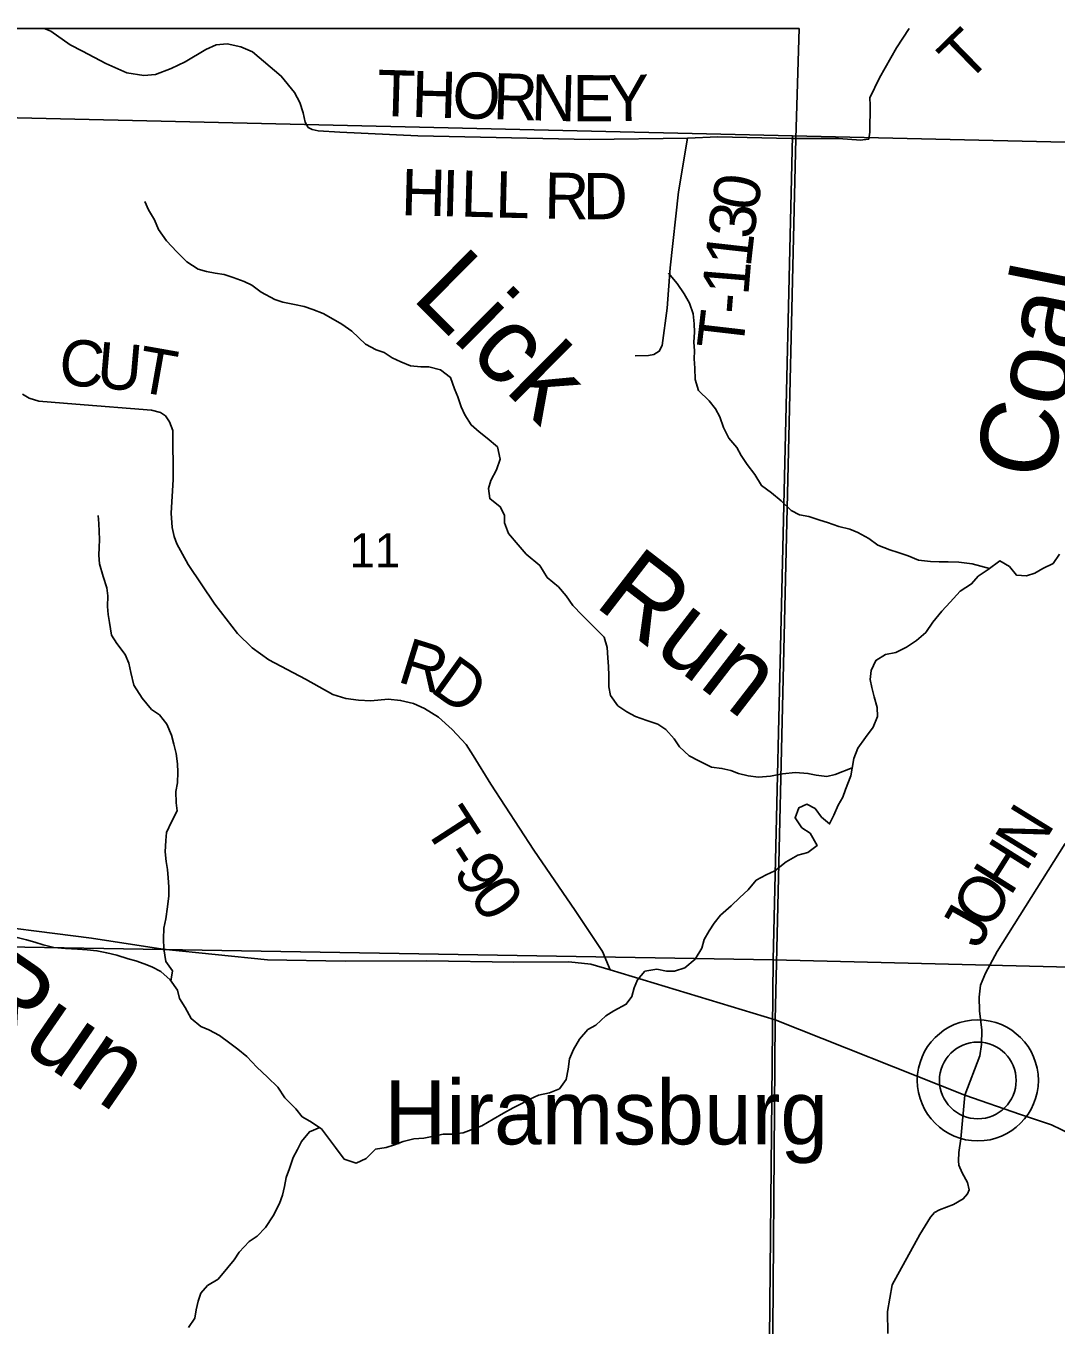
# Model space of a CAD drawing. Extents: x -452339 to 6403467, y -1 to 1814750.
# Drawn here: x -70035 to -63350, y 1554727 to 1563158 of the extents above; entities that cross this region are included whole.
import ezdxf

# ---------------------------------------------------------------- set-up
doc = ezdxf.new("R2010")
doc.units = 0
for name, color, linetype in [('GM_X_Adjacent_County_Text', 7, 'Continuous'), ('GM_X_Corporation', 7, 'Continuous'), ('GM_X_County_Road', 7, 'Continuous'), ('GM_X_County_Road_Text', 7, 'Continuous'), ('GM_X_County_ROW', 7, 'Continuous'), ('GM_X_Major_Lake', 7, 'Continuous'), ('GM_X_Major_Lake_Text', 7, 'Continuous'), ('GM_X_Section', 7, 'Continuous'), ('GM_X_Section_Text', 7, 'Continuous'), ('GM_X_Township_Road_Text', 7, 'Continuous'), ('GM_X_Unincorporated_Location', 7, 'Continuous')]:
    doc.layers.add(name, color=color, linetype=linetype)

msp = doc.modelspace()

# ---------------------------------------------------------------- linework, layer by layer
at = {"layer": 'GM_X_County_Road'}
msp.add_lwpolyline([(-63191, 1555935.7), (-63379.6, 1556027.1), (-63580.2, 1556094.3), (-63942.9, 1556218.4), (-65173, 1556706.7), (-66244.5, 1557031.8), (-66368.8, 1557069.7), (-66513.1, 1557085.1), (-66869.7, 1557081.3), (-67432.7, 1557090.6), (-67963.6, 1557088.1), (-68468.5, 1557097.7), (-69147.9, 1557166.6), (-69611, 1557238.6), (-70462.9, 1557344.8)], dxfattribs=at)
at = {"layer": 'GM_X_County_Road_Text'}
for radius in [392.8, 249]:
    msp.add_circle((-63857.5, 1556314.4), radius, dxfattribs=at)
at = {"layer": 'GM_X_County_ROW'}
for points in [[(-65068.9, 1562427.7), (-65544.7, 1562437.4), (-65741.6, 1562428.6), (-66376.5, 1562420.9), (-67492.1, 1562444.3), (-67998.1, 1562468.4), (-68138.1, 1562477.3), (-68178.1, 1562485), (-68204.2, 1562498.9), (-68222.5, 1562532.8), (-68236.9, 1562594.8), (-68257.3, 1562660.7), (-68291.8, 1562726.6), (-68378.5, 1562832), (-68565.5, 1562988.8), (-68641.7, 1563022.3), (-68729.8, 1563041.6), (-68801.7, 1563035.1), (-68867.5, 1563004.5), (-69002.9, 1562925.3), (-69092.5, 1562882.6), (-69194.2, 1562843.7), (-69270.1, 1562837.1), (-69380.2, 1562854.3), (-69516.6, 1562913.3), (-69669.1, 1562994.3), (-69749.3, 1563035.7), (-69873.9, 1563124.9), (-69916.9, 1563140.5)], [(-64303.6, 1563140.5), (-64385.6, 1563015.4), (-64496.1, 1562820.2), (-64558.9, 1562692.2), (-64557.1, 1562643), (-64558.9, 1562469), (-64565.9, 1562423.4), (-64603.6, 1562418.2)], [(-66080.9, 1561017.1), (-65994.9, 1561019.8), (-65960.9, 1561026.1), (-65925.1, 1561046.4), (-65905.3, 1561084.6), (-65873.1, 1561325.3), (-65855.1, 1561587.9), (-65800.7, 1562081.2), (-65741.6, 1562428.6)], [(-64603.6, 1562418.2), (-64616.9, 1562416.3), (-64762.7, 1562426.9), (-65038.6, 1562427.1), (-65068.9, 1562427.7)], [(-66244.5, 1557031.8), (-66293, 1557151.8), (-66470.8, 1557416.9), (-66739.5, 1557809.6), (-67018.4, 1558236.3), (-67133.7, 1558423.7), (-67178.2, 1558493.5), (-67268.9, 1558593), (-67357.4, 1558672.5), (-67449.7, 1558727.9), (-67520, 1558761.4), (-67604.1, 1558780.8), (-67684.1, 1558788.2), (-67797.9, 1558777.3), (-67877.9, 1558782.7), (-67960, 1558794), (-68044.1, 1558819.4), (-68220.8, 1558918.3), (-68459.6, 1559044.6), (-68568.1, 1559121.9), (-68662.7, 1559215.4), (-68810, 1559404.6), (-68981.7, 1559661.8), (-69056.7, 1559797.5), (-69073, 1559845.4), (-69087.4, 1559903.4), (-69092.1, 1559995.6), (-69079.6, 1560214.1), (-69081.9, 1560532.6), (-69104.3, 1560588.6), (-69130.5, 1560628.4), (-69162.7, 1560648.2), (-69220.7, 1560663.8), (-69712.8, 1560704), (-69952.8, 1560722.2), (-70015, 1560741.7), (-70057.1, 1560767.5)], [(-63942.9, 1556218.4), (-63845.2, 1556474.6), (-63834.4, 1556546.9), (-63832.1, 1556641.1), (-63846.2, 1556765.2), (-63847.8, 1556855.3), (-63839.1, 1556931.6), (-63808.5, 1557010.3), (-63733, 1557152), (-63291.2, 1557851.4)]]:
    msp.add_lwpolyline(points, dxfattribs=at)
at = {"layer": 'GM_X_Section'}
msp.add_lwpolyline([(-63942.9, 1556218.4), (-63968.8, 1555936), (-63980.8, 1555845.8), (-63982.7, 1555793.7), (-63980.7, 1555763.7), (-63958.6, 1555715.6), (-63924.6, 1555651.6), (-63914.6, 1555605.5), (-63924.5, 1555577.4), (-63952.5, 1555545.3), (-64016.4, 1555509.2), (-64106.4, 1555475), (-64138.4, 1555456.9), (-64164.3, 1555426.8), (-64234.2, 1555314.5), (-64413.9, 1554988.8), (-64443.7, 1554815.5), (-64441.5, 1554672.4)], dxfattribs=at)
at = {"layer": 'GM_X_Section_Text'}
msp.add_lwpolyline([(-65016.9, 1563140.5), (-75200.9, 1563140.5), (-75200.9, 1547985.7), (-65249.9, 1547985.7), (-65216.2, 1549772.3), (-65189.8, 1554406.9), (-65173, 1556706.7), (-65038.6, 1562427.1)], close=True, dxfattribs=at)
at = {"layer": 'GM_X_Township_Road_Text'}
for points in [[(-64672.2, 1558343.1), (-64782.4, 1558300), (-64838.3, 1558287.8), (-64906.3, 1558295.5), (-64960.3, 1558307.4), (-65040.3, 1558313.1), (-65124.3, 1558304.8), (-65204.2, 1558288.5), (-65280.1, 1558282.2), (-65348.1, 1558292), (-65410.2, 1558305.8), (-65460.2, 1558325.7), (-65518.2, 1558339.5), (-65586.2, 1558347.3), (-65668.3, 1558389.1), (-65730.4, 1558420.9), (-65794.5, 1558478.8), (-65828.7, 1558530.7), (-65882.9, 1558592.6), (-65934.9, 1558626.5), (-66005, 1558650.3), (-66079, 1558676.1), (-66135.1, 1558705.9), (-66193.2, 1558745.8), (-66241.4, 1558811.7), (-66251.5, 1558869.7), (-66251.8, 1558941.9), (-66254, 1558999.9), (-66258.1, 1559056), (-66262.3, 1559124.1), (-66282.5, 1559192.1), (-66352.7, 1559260), (-66424.9, 1559333.8), (-66487.1, 1559397.7), (-66529.3, 1559459.6), (-66579.4, 1559517.5), (-66651.6, 1559579.4), (-66699.8, 1559655.3), (-66788, 1559729.1), (-66840.1, 1559791), (-66904.3, 1559864.9), (-66930.5, 1559932.9), (-66928.7, 1559983), (-66956.8, 1560037), (-67025, 1560090.8), (-67033.2, 1560154.9), (-67017.3, 1560207), (-66981.6, 1560277.2), (-66957.8, 1560345.4), (-66974, 1560425.4), (-67042.2, 1560483.3), (-67094.3, 1560523.2), (-67146.4, 1560569), (-67186.6, 1560633), (-67210.7, 1560687), (-67232.9, 1560751), (-67253.1, 1560803), (-67279.3, 1560877), (-67345.4, 1560926.8), (-67421.4, 1560946.6), (-67473.4, 1560946.4), (-67539.4, 1560952.2), (-67601.5, 1560978), (-67659.5, 1561003.8), (-67711.6, 1561037.7), (-67763.6, 1561055.6), (-67831.7, 1561093.4), (-67919.9, 1561177.2), (-67986, 1561223), (-68056.1, 1561262.8), (-68106.2, 1561290.7), (-68174.3, 1561318.5), (-68230.3, 1561336.3), (-68292.3, 1561350.1), (-68368.3, 1561365.9), (-68420.4, 1561381.7), (-68508.5, 1561429.5), (-68568.6, 1561475.3), (-68618.6, 1561499.2), (-68690.7, 1561525), (-68748.7, 1561544.8), (-68806.7, 1561552.6), (-68864.7, 1561564.4), (-68916.8, 1561580.3), (-68990.9, 1561626.1), (-69057, 1561691.9), (-69123.2, 1561763.8), (-69175.4, 1561837.7), (-69201.6, 1561899.7), (-69239.8, 1561963.6), (-69263.9, 1562017.6)], [(-63782.6, 1559637.1), (-63894.9, 1559666.9), (-63980.9, 1559678.6), (-64050.9, 1559680.4), (-64108.9, 1559680.2), (-64164.9, 1559682), (-64242.9, 1559691.7), (-64308.9, 1559719.6), (-64375, 1559741.4), (-64429, 1559757.2), (-64507.1, 1559789), (-64565.2, 1559830.8), (-64637.3, 1559870.6), (-64689.3, 1559892.5), (-64759.3, 1559910.3), (-64833.4, 1559936.1), (-64883.4, 1559949.9), (-64953.5, 1559973.7), (-65015.5, 1559985.5), (-65069.5, 1560013.4), (-65133.7, 1560075.2), (-65195.8, 1560127.1), (-65262, 1560174.9), (-65304.2, 1560246.9), (-65354.3, 1560312.8), (-65392.5, 1560370.7), (-65420.6, 1560422.7), (-65472.8, 1560482.6), (-65509, 1560552.6), (-65531.2, 1560620.6), (-65559.4, 1560672.6), (-65601.5, 1560724.5), (-65669.7, 1560792.3), (-65691.9, 1560864.4), (-65694.1, 1560936.4), (-65698.3, 1560998.5), (-65696.4, 1561048.6), (-65700.6, 1561104.6), (-65696.8, 1561170.7), (-65699, 1561224.8), (-65705.2, 1561288.8), (-65729.4, 1561358.8), (-65763.5, 1561418.8), (-65809.7, 1561486.7), (-65865.9, 1561552.6)], [(-69094.7, 1556959), (-69084.7, 1557025.3), (-69126.9, 1557085.2), (-69141.1, 1557169.3), (-69143.3, 1557233.4), (-69141.6, 1557303.5), (-69127.7, 1557363.7), (-69116, 1557441.8), (-69108.2, 1557512), (-69108.4, 1557570), (-69112.6, 1557630.1), (-69116.7, 1557684.2), (-69124.9, 1557734.2), (-69131.1, 1557798.3), (-69127.3, 1557872.4), (-69123.5, 1557924.5), (-69091.7, 1557992.7), (-69053.9, 1558065), (-69060.1, 1558115), (-69062.3, 1558189.1), (-69052.5, 1558245.2), (-69050.7, 1558315.4), (-69050.9, 1558369.4), (-69061.1, 1558435.5), (-69075.3, 1558497.5), (-69091.4, 1558555.6), (-69121.6, 1558625.6), (-69169.8, 1558687.5), (-69219.9, 1558721.4), (-69282.1, 1558795.3), (-69334.3, 1558879.2), (-69354.6, 1558961.3), (-69366.8, 1559023.3), (-69390.9, 1559079.3), (-69445.1, 1559149.2), (-69479.3, 1559203.2), (-69493.5, 1559285.3), (-69501.7, 1559337.3), (-69505.8, 1559389.4), (-69504.1, 1559459.5), (-69510.2, 1559511.5), (-69534.4, 1559585.6), (-69558.7, 1559667.6), (-69562.8, 1559723.7), (-69561, 1559773.7), (-69557.2, 1559825.8), (-69561.5, 1559929.9), (-69567.6, 1559980)], [(-63327.4, 1559728.9), (-63369.2, 1559668.7), (-63435, 1559636.4), (-63486.9, 1559606.2), (-63540.9, 1559590), (-63606.8, 1559593.8), (-63653, 1559649.7), (-63715.1, 1559685.5), (-63790.9, 1559631.2), (-63854.7, 1559586.9), (-63898.5, 1559536.7), (-63972.4, 1559490.4), (-64036.1, 1559418.1), (-64091.9, 1559359.8), (-64149.7, 1559287.5), (-64195.5, 1559221.3), (-64255.3, 1559169), (-64321.1, 1559126.7), (-64389, 1559092.4), (-64456.9, 1559078.2), (-64518.8, 1559039.9), (-64550.6, 1558975.7), (-64556.4, 1558915.6), (-64546.2, 1558863.6), (-64530, 1558803.5), (-64511.8, 1558735.5), (-64507.7, 1558675.4), (-64537.4, 1558607.2), (-64587.2, 1558541), (-64637, 1558470.7), (-64662.8, 1558404.5), (-64672.6, 1558340.4), (-64682.4, 1558290.3), (-64716.1, 1558202.1), (-64734, 1558151.9), (-64763.8, 1558101.8), (-64791.6, 1558035.6), (-64819.4, 1557979.4), (-64871.5, 1558023.3), (-64913.7, 1558079.2), (-64967.7, 1558107.1), (-65019.6, 1558082.8), (-65043.4, 1558018.7), (-64999.2, 1557954.7), (-64945.2, 1557918.9), (-64900.9, 1557838.9), (-64960.8, 1557792.6), (-65024.7, 1557776.4), (-65100.5, 1557732.1), (-65174.3, 1557675.7), (-65230.2, 1557649.5), (-65296.1, 1557613.2), (-65347.9, 1557551), (-65401.7, 1557502.7), (-65457.5, 1557448.4), (-65527.3, 1557386.1), (-65569.1, 1557335.9), (-65600.9, 1557285.7), (-65634.7, 1557229.5), (-65648.6, 1557173.4), (-65692.3, 1557101.1), (-65758.1, 1557044.8), (-65826, 1557022.5), (-65878, 1557024.4), (-65940, 1557036.2), (-66018, 1557023.9), (-66065.8, 1556967.6), (-66087.6, 1556915.5), (-66103.4, 1556859.3), (-66139.3, 1556809.1), (-66219.1, 1556766.8), (-66271, 1556732.6), (-66336.8, 1556672.3), (-66388.7, 1556646), (-66442.4, 1556581.8), (-66482.2, 1556515.5), (-66508, 1556455.4), (-66515.8, 1556387.2), (-66529.6, 1556321.1), (-66573.4, 1556260.9), (-66637.3, 1556234.6), (-66709.2, 1556218.3), (-66765.1, 1556192.1), (-66817, 1556163.9), (-66872.9, 1556137.6), (-66936.8, 1556101.4), (-67002.6, 1556063.1), (-67076.4, 1556020.8), (-67146.3, 1555994.5), (-67198.3, 1555974.3), (-67272.2, 1555966), (-67328.2, 1555965.8)], [(-67328.2, 1555965.8), (-67400.1, 1555951.6), (-67454, 1555939.4), (-67518, 1555935.1), (-67587.9, 1555918.9), (-67643.8, 1555896.6), (-67697.8, 1555878.4), (-67767.7, 1555868.2), (-67827.5, 1555807.9), (-67891.4, 1555777.6), (-67969.4, 1555803.4), (-68025.6, 1555879.3), (-68077.8, 1555949.2), (-68118, 1556001.2), (-68192.1, 1556051), (-68242.1, 1556078.8), (-68284.3, 1556130.8), (-68354.5, 1556200.6), (-68400.7, 1556270.6), (-68468.8, 1556336.4), (-68537, 1556400.3), (-68601.2, 1556470.2), (-68659.3, 1556518), (-68711.4, 1556555.9), (-68779.6, 1556605.7), (-68847.6, 1556643.6), (-68899.7, 1556663.4), (-68963.8, 1556715.3), (-69002, 1556787.2), (-69038.2, 1556845.2), (-69052.3, 1556899.2), (-69100.5, 1556967.2), (-69160.7, 1557021), (-69218.8, 1557050.9), (-69268.8, 1557070.7), (-69322.8, 1557090.6), (-69372.9, 1557104.4), (-69444.9, 1557128.2), (-69510.9, 1557142), (-69574.9, 1557155.8), (-69638.9, 1557161.6), (-69700.9, 1557165.4), (-69778.9, 1557171.1), (-69854.9, 1557176.9), (-69922.9, 1557194.7), (-69978.9, 1557212.5), (-70033, 1557226.4), (-70101, 1557244.1)], [(-68128, 1556007.9), (-68195.9, 1555980.9), (-68247.6, 1555918.6), (-68273.5, 1555866.4), (-68301.3, 1555814.3), (-68325.1, 1555742.1), (-68346.9, 1555683.9), (-68356.7, 1555625.8), (-68370.5, 1555569.7), (-68390.4, 1555515.5), (-68430.1, 1555435.3), (-68479.8, 1555359), (-68535.6, 1555304.7), (-68587.5, 1555268.5), (-68651.3, 1555200.2), (-68683.1, 1555150), (-68724.9, 1555099.8), (-68788.7, 1555025.5), (-68856.5, 1554983.2), (-68900.4, 1554933), (-68918.2, 1554880.9), (-68930, 1554824.7), (-68939.9, 1554772.6), (-68979.6, 1554710.4)]]:
    msp.add_lwpolyline(points, dxfattribs=at)
at = {"layer": 'GM_X_Unincorporated_Location'}
for points in [[(-65059.8, 1562444.8), (-65186.4, 1557097.3), (-70427.3, 1557184.9), (-70371.2, 1562567.6)], [(-59752.5, 1562321.9), (-59755.1, 1561995.7), (-59844.9, 1556964.8), (-65186.4, 1557097.3), (-65059.8, 1562444.8)], [(-70427.3, 1557184.9), (-65186.4, 1557097.3), (-65238.6, 1551724.6), (-70513.9, 1551851.8)], [(-65186.4, 1557097.3), (-59844.9, 1556964.8), (-59852, 1556682.6), (-59917, 1551575.9), (-65238.6, 1551724.6)]]:
    msp.add_lwpolyline(points, close=True, dxfattribs=at)

# ---------------------------------------------------------------- texts
at = {"layer": 'GM_X_Adjacent_County_Text'}
msp.add_text('Hiramsburg', height=416.67, rotation=0.00001, dxfattribs=at).set_placement((-67709.1, 1555899.4))
at = {"layer": 'GM_X_Corporation'}
for s, height, rotation, p in [('Lick', 500.1, 315.21429, (-67539.8, 1561391.2)), ('Coal', 500.16, 78.77792, (-63391.1, 1560194.8)), ('Run', 500.11, 322.31583, (-66355.9, 1559400.6)), ('Run', 500.11, 325.43818, (-70472.2, 1556798))]:
    msp.add_text(s, height=height, rotation=rotation, dxfattribs=at).set_placement(p)
at = {"layer": 'GM_X_Major_Lake'}
msp.add_text('11', height=220.83, rotation=0.00001, dxfattribs=at).set_placement((-67935.7, 1559644.3))
at = {"layer": 'GM_X_Major_Lake_Text'}
for s, rotation, p in [('T', 44.32418, (-63931, 1562778.2)), ('T', 358.37126, (-67759.2, 1562574.1)), ('H', 358.36779, (-67534.9, 1562567.7)), ('O', 358.36921, (-67271, 1562560.2)), ('R', 358.3679, (-67007.1, 1562552.7)), ('N', 358.55309, (-66759.8, 1562545.7)), ('E', 359.80928, (-66488.7, 1562538.9)), ('Y', 1.0853, (-66257, 1562538.2)), ('H', 358.54642, (-67603.5, 1561930.7)), ('I', 358.54906, (-67339.6, 1561924)), ('L', 358.55144, (-67216.4, 1561920.9)), ('L', 358.60042, (-66991.8, 1561915.2)), ('R', 358.97735, (-66672.9, 1561907.6)), ('D', 0.20106, (-66419.6, 1561903.1)), ('0', 80.72247, (-65290, 1561948.9)), ('3', 83.12994, (-65311.6, 1561768.7)), ('1', 83.57533, (-65332.2, 1561585.7)), ('1', 85.29037, (-65347.2, 1561403.8)), ('-', 85.495, (-65356.8, 1561281.3)), ('T', 83.3943, (-65383.8, 1561046.5)), ('C', 355.1388, (-69829, 1560831.5)), ('U', 355.03247, (-69583.6, 1560810.6)), ('T', 349.94585, (-69327.6, 1560788.7)), ('R', 342.8043, (-67633, 1558904.5)), ('D', 324.45767, (-67420.3, 1558842.9)), ('T', 302.89128, (-67460, 1557962.1)), ('N', 58.32224, (-63504.5, 1557729.3)), ('-', 303.01312, (-67337.7, 1557773.1)), ('H', 57.83668, (-63646.5, 1557503.5)), ('9', 303.41272, (-67269.4, 1557667.9)), ('O', 57.98727, (-63786.3, 1557279.8)), ('0', 304.58263, (-67163.9, 1557508.1)), ('J', 60.63294, (-63853.5, 1557160.2))]:
    msp.add_text(s, height=300, rotation=rotation, dxfattribs=at).set_placement(p)

doc.saveas('drawing.dxf')
